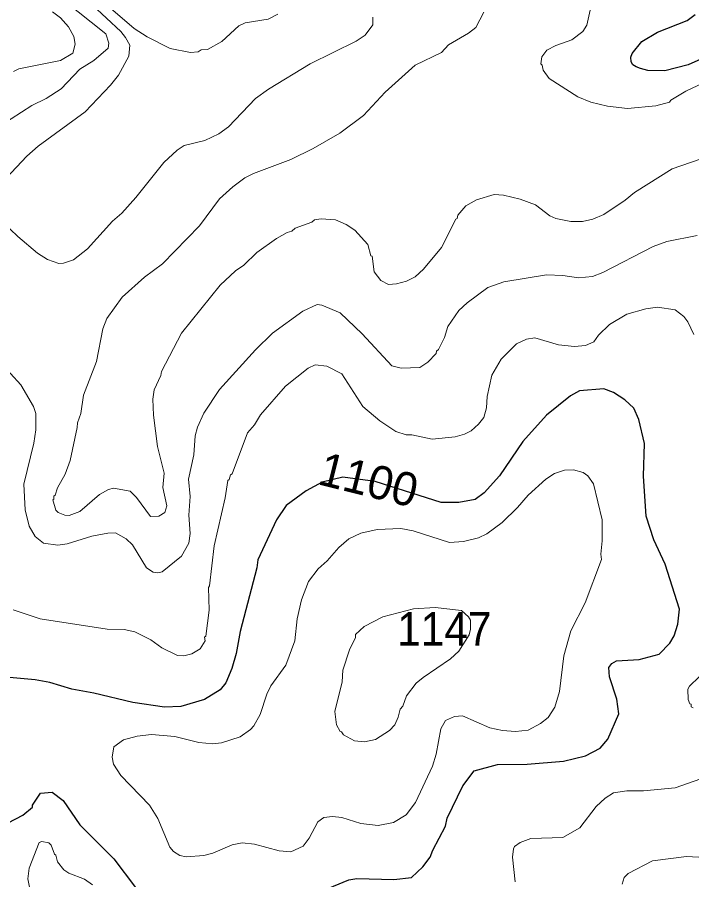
# Model space of a CAD drawing. Extents: x 447.8 to 473.9, y 7733.1 to 7760.8.
# Drawn here: x 470.955 to 472.572, y 7751.643 to 7753.711 of the extents above; entities that cross this region are included whole.
import ezdxf
from ezdxf.enums import TextEntityAlignment as Align

# ---------------------------------------------------------------- set-up
doc = ezdxf.new("R2010")
doc.units = 0
doc.header["$LTSCALE"] = 0.032
doc.layers.add('1', color=7, linetype='Continuous', lineweight=25)
doc.layers.add('2', color=7, linetype='Continuous', lineweight=13)
doc.layers.add('21', color=7, linetype='Continuous')
doc.layers.add('61', color=7, linetype='Continuous')

msp = doc.modelspace()

# ---------------------------------------------------------------- linework, layer by layer
at = {"layer": '1'}
for points in [[(472.9088, 7753.745), (472.8961, 7753.7065), (472.881, 7753.6353), (472.8769, 7753.6269), (472.852, 7753.6004), (472.8228, 7753.6073), (472.749, 7753.6401), (472.711, 7753.6473), (472.6487, 7753.6351), (472.5631, 7753.597), (472.5076, 7753.5821), (472.4669, 7753.5833), (472.4495, 7753.5877), (472.4391, 7753.5922), (472.4305, 7753.5972), (472.4266, 7753.604), (472.4257, 7753.6151), (472.4289, 7753.6242), (472.4527, 7753.6529), (472.4902, 7753.6754), (472.5608, 7753.7035), (472.5805, 7753.7173)], [(472.446, 7752.171), (472.4942, 7752.1843), (472.5192, 7752.2108), (472.5298, 7752.2278), (472.5387, 7752.2562), (472.5426, 7752.292), (472.5084, 7752.3995), (472.4809, 7752.4579), (472.4626, 7752.5153), (472.4561, 7752.611), (472.4585, 7752.6888), (472.4455, 7752.7469), (472.4329, 7752.7734), (472.412, 7752.7938), (472.3847, 7752.8114), (472.3611, 7752.8201), (472.3031, 7752.8154), (472.2815, 7752.8034), (472.224, 7752.757), (472.1673, 7752.6935), (472.1112, 7752.6117), (472.074, 7752.5712), (472.0526, 7752.5549), (472.0137, 7752.5478), (471.9712, 7752.548), (471.8134, 7752.5984), (471.7358, 7752.6081), (471.6858, 7752.5963), (471.6476, 7752.5759), (471.5998, 7752.5403), (471.5769, 7752.5063), (471.532, 7752.4102), (471.5295, 7752.391), (471.4894, 7752.2387), (471.4797, 7752.1854), (471.4691, 7752.1494), (471.4551, 7752.1152), (471.4417, 7752.0986), (471.4041, 7752.0754), (471.3472, 7752.0587), (471.3082, 7752.0572), (471.2317, 7752.0684), (471.1388, 7752.0909), (471.0859, 7752.1005), (471.033, 7752.1165), (470.9977, 7752.1229), (470.9278, 7752.1293)], [(471.6897, 7751.6186), (471.7496, 7751.6434), (471.7688, 7751.6467), (471.8581, 7751.6443), (471.8998, 7751.649), (471.9276, 7751.6746), (471.9449, 7751.6971), (471.9512, 7751.7143), (471.9815, 7751.7718), (471.9855, 7751.7907), (472.0229, 7751.8687), (472.0502, 7751.9041), (472.1066, 7751.9193), (472.1771, 7751.9201), (472.2645, 7751.9274), (472.3177, 7751.9403), (472.3525, 7751.9591), (472.3706, 7751.98), (472.3974, 7752.0408), (472.3928, 7752.0761), (472.3751, 7752.1297), (472.3736, 7752.1522), (472.3803, 7752.1615), (472.3916, 7752.1682), (472.446, 7752.171)], [(470.9332, 7751.7801), (470.968, 7751.7981), (470.9913, 7751.8174), (470.9919, 7751.8224), (471.0107, 7751.8508), (471.0384, 7751.8529), (471.0648, 7751.8333), (471.1052, 7751.7753), (471.1869, 7751.6935), (471.2387, 7751.6249), (471.26, 7751.6045), (471.2943, 7751.5812), (471.3126, 7751.573), (471.3483, 7751.5698), (471.3969, 7751.5746), (471.4292, 7751.5577), (471.4444, 7751.5285), (471.4469, 7751.5104), (471.4387, 7751.4728), (471.4326, 7751.4199), (471.4358, 7751.3819), (471.4446, 7751.3631), (471.4615, 7751.3423), (471.4764, 7751.3382)]]:
    msp.add_lwpolyline(points, dxfattribs=at)
at = {"layer": '2'}
for points in [[(471.0656, 7753.7523), (471.1675, 7753.6712), (471.1743, 7753.6491), (471.1728, 7753.637), (471.1385, 7753.6073), (471.1052, 7753.5862)], [(470.9281, 7753.325), (470.9776, 7753.3778), (471.005, 7753.4015), (471.118, 7753.4845), (471.1786, 7753.5484), (471.1978, 7753.5724), (471.2226, 7753.6177), (471.2248, 7753.644), (471.2148, 7753.6625), (471.2029, 7753.6767), (471.1349, 7753.7405)], [(471.5794, 7753.7182), (471.5569, 7753.7066), (471.5014, 7753.6972), (471.486, 7753.6905), (471.4454, 7753.6531), (471.4113, 7753.6333), (471.3955, 7753.6331), (471.3885, 7753.6283), (471.3703, 7753.6267), (471.3215, 7753.6356), (471.2664, 7753.6641), (471.235, 7753.6838), (471.1672, 7753.742)], [(471.8077, 7753.7111), (471.8076, 7753.6928), (471.7891, 7753.6676), (471.7673, 7753.6538), (471.657, 7753.5994), (471.5575, 7753.5384), (471.526, 7753.5158), (471.4611, 7753.4485), (471.4379, 7753.4314), (471.4049, 7753.4157), (471.3548, 7753.4034), (471.3387, 7753.3926), (471.3061, 7753.3628), (471.239, 7753.2785), (471.2054, 7753.2409), (471.1831, 7753.2218), (471.1233, 7753.1556), (471.0898, 7753.1291), (471.066, 7753.121), (471.0548, 7753.1209), (471.0273, 7753.1302), (471.0037, 7753.1453), (470.9561, 7753.1852), (470.9196, 7753.2202)], [(470.9462, 7753.5805), (470.9584, 7753.5874), (471.0583, 7753.6072), (471.0881, 7753.6248), (471.0942, 7753.646), (471.091, 7753.6648), (471.0779, 7753.6878), (471.0584, 7753.7098), (471.0397, 7753.7236)], [(471.2802, 7752.7951), (471.2819, 7752.7574), (471.2915, 7752.6821), (471.3074, 7752.6182), (471.3043, 7752.5839), (471.3139, 7752.5394), (471.3088, 7752.5234), (471.2946, 7752.5149), (471.2746, 7752.5141), (471.2409, 7752.5599), (471.2256, 7752.5749), (471.1859, 7752.5823), (471.1741, 7752.5788), (471.1525, 7752.5665), (471.1046, 7752.5262), (471.0798, 7752.5165), (471.0688, 7752.5172), (471.0527, 7752.5238), (471.0474, 7752.5292), (471.0399, 7752.554), (471.0429, 7752.556), (471.043, 7752.5626), (471.0462, 7752.5651), (471.0518, 7752.5832), (471.0695, 7752.6153), (471.0821, 7752.6487), (471.099, 7752.7273), (471.0991, 7752.7385), (471.107, 7752.7609), (471.1136, 7752.8048), (471.1447, 7752.886), (471.1602, 7752.9636), (471.1696, 7752.9886), (471.2065, 7753.0399), (471.2599, 7753.0878), (471.3035, 7753.1201), (471.3922, 7753.2112), (471.4399, 7753.2758), (471.4715, 7753.3045), (471.5007, 7753.326), (471.5217, 7753.3366), (471.6108, 7753.3699), (471.6643, 7753.3963), (471.7282, 7753.4332), (471.7854, 7753.4754), (471.8373, 7753.5313), (471.9086, 7753.5961), (471.9721, 7753.6263), (471.9885, 7753.6448), (472.0368, 7753.6724), (472.0545, 7753.6867), (472.0737, 7753.7229)], [(472.3285, 7753.7276), (472.3202, 7753.6918), (472.311, 7753.6771), (472.2849, 7753.6569), (472.2466, 7753.6433), (472.2247, 7753.6322), (472.213, 7753.6164), (472.2101, 7753.599), (472.2132, 7753.5963), (472.2161, 7753.5842)], [(471.1052, 7753.5862), (471.0599, 7753.5396), (471.0239, 7753.5162), (470.9903, 7753.4994), (470.9159, 7753.4518), (470.8829, 7753.4407)], [(472.2161, 7753.5842), (472.2305, 7753.5644), (472.2992, 7753.5199), (472.3302, 7753.5077), (472.37, 7753.4977), (472.4178, 7753.492)], [(472.4178, 7753.492), (472.486, 7753.4985), (472.5186, 7753.5077), (472.5217, 7753.5124), (472.5577, 7753.5335), (472.6277, 7753.5665)], [(472.5919, 7753.371), (472.5253, 7753.3474), (472.4346, 7753.2911), (472.4123, 7753.2725), (472.3614, 7753.2382), (472.3353, 7753.2268), (472.3101, 7753.2212), (472.2818, 7753.2212), (472.2464, 7753.2287), (472.2321, 7753.235), (472.1972, 7753.2611), (472.161, 7753.2745), (472.1209, 7753.2842), (472.0986, 7753.2859), (472.0558, 7753.273), (472.0305, 7753.2588), (472.0109, 7753.2367), (472.0095, 7753.2286), (472.0061, 7753.2266), (471.9721, 7753.1588), (471.9292, 7753.107), (471.9091, 7753.089), (471.8884, 7753.0786), (471.8642, 7753.0717), (471.8452, 7753.0705), (471.827, 7753.0799), (471.811, 7753.1004), (471.806, 7753.138), (471.8029, 7753.139), (471.7955, 7753.1665), (471.7646, 7753.2008), (471.7437, 7753.2137), (471.7178, 7753.225), (471.6834, 7753.2274), (471.6676, 7753.2251), (471.6612, 7753.22), (471.6216, 7753.2056), (471.6133, 7753.1978), (471.6024, 7753.1948), (471.5769, 7753.1805), (471.5292, 7753.147), (471.498, 7753.1165), (471.4779, 7753.103), (471.4414, 7753.0688)], [(470.9996, 7752.7217), (470.9949, 7752.6895), (470.9707, 7752.5913), (470.974, 7752.5298), (470.9837, 7752.4913), (470.998, 7752.466), (471.0181, 7752.45), (471.0521, 7752.4452), (471.0746, 7752.4483), (471.1339, 7752.4667), (471.1724, 7752.4739), (471.1906, 7752.4746), (471.2162, 7752.4609), (471.2312, 7752.4459), (471.265, 7752.3907), (471.2811, 7752.3806), (471.2918, 7752.3788), (471.3026, 7752.3816), (471.3489, 7752.4192), (471.3667, 7752.4503), (471.3692, 7752.473), (471.366, 7752.5176), (471.3692, 7752.562), (471.3652, 7752.6038), (471.378, 7752.6619), (471.3813, 7752.7071), (471.3873, 7752.7282), (471.4025, 7752.7619), (471.4402, 7752.8184), (471.5262, 7752.914), (471.5671, 7752.9533), (471.6398, 7753.0066), (471.6743, 7753.0223), (471.6848, 7753.0204), (471.729, 7753.0022), (471.7817, 7752.952), (471.8534, 7752.8756), (471.8751, 7752.8695), (471.9203, 7752.8713), (471.9396, 7752.8842), (471.9595, 7752.9048), (471.9601, 7752.9107), (471.9646, 7752.9141), (471.979, 7752.9434), (471.9875, 7752.9699), (472.0135, 7753.0076), (472.0334, 7753.0267), (472.0831, 7753.063), (472.1218, 7753.0767), (472.2241, 7753.0936), (472.2633, 7753.092), (472.3007, 7753.0864), (472.334, 7753.0898), (472.3588, 7753.0991), (472.4796, 7753.1611), (472.5127, 7753.1736), (472.5847, 7753.1881)], [(471.4414, 7753.0688), (471.3488, 7752.9539), (471.3004, 7752.8613), (471.2993, 7752.8521), (471.2831, 7752.818), (471.2802, 7752.7951)], [(470.9454, 7752.2903), (471.0096, 7752.2687), (471.1706, 7752.2444), (471.2116, 7752.2431), (471.2366, 7752.2376), (471.275, 7752.2184), (471.3013, 7752.1989), (471.3392, 7752.1808), (471.3541, 7752.1798), (471.3737, 7752.1845), (471.3938, 7752.1967), (471.4052, 7752.2161), (471.4038, 7752.2246), (471.4068, 7752.2275), (471.4148, 7752.2896), (471.4132, 7752.3436), (471.4158, 7752.3479), (471.4269, 7752.4439), (471.4533, 7752.5586), (471.4598, 7752.6004), (471.4629, 7752.6026), (471.4663, 7752.6141), (471.4699, 7752.6164), (471.5068, 7752.7147), (471.524, 7752.7339), (471.5383, 7752.7577), (471.5979, 7752.8268), (471.6527, 7752.87), (471.6696, 7752.8778), (471.697, 7752.8747), (471.7328, 7752.8562), (471.7838, 7752.7775), (471.8239, 7752.7431), (471.8624, 7752.7175), (471.8874, 7752.7097), (471.901, 7752.7096), (471.95, 7752.6994), (472.0052, 7752.7049), (472.0276, 7752.7117), (472.043, 7752.7197), (472.061, 7752.7353), (472.0736, 7752.7512), (472.08, 7752.7746), (472.0818, 7752.8014), (472.0931, 7752.8526), (472.1151, 7752.8914), (472.1518, 7752.9278), (472.176, 7752.9396), (472.1955, 7752.9422), (472.253, 7752.9253), (472.291, 7752.9213), (472.3171, 7752.9244), (472.3372, 7752.9325), (472.3489, 7752.9488), (472.3749, 7752.9747), (472.4165, 7752.9989), (472.4618, 7753.012)], [(472.4618, 7753.012), (472.4901, 7753.0158), (472.5326, 7753.0099), (472.5528, 7752.9936), (472.5623, 7752.9811), (472.577, 7752.95)], [(470.914, 7752.8767), (470.939, 7752.8569), (470.9633, 7752.8301), (470.994, 7752.7777), (470.9996, 7752.7609), (470.9996, 7752.7217)], [(472.5897, 7752.1299), (472.5663, 7752.1071), (472.5628, 7752.1001), (472.5636, 7752.0752), (472.5676, 7752.0654), (472.5706, 7752.0641), (472.5709, 7752.0575), (472.5754, 7752.0553)], [(473.0463, 7751.9922), (473.0328, 7751.9875), (472.9981, 7751.982), (472.9687, 7751.9842), (472.9003, 7752.0157), (472.8503, 7752.0337), (472.8244, 7752.0395), (472.7974, 7752.0368), (472.7777, 7752.0251), (472.7632, 7752.0047), (472.7648, 7751.9286), (472.7807, 7751.8267), (472.7768, 7751.8013), (472.7679, 7751.7755), (472.7265, 7751.7264), (472.6935, 7751.7098), (472.6369, 7751.6986), (472.6037, 7751.6965), (472.5595, 7751.6988), (472.4777, 7751.6883), (472.4194, 7751.6587), (472.4102, 7751.6484), (472.4054, 7751.6324)], [(472.594, 7751.8851), (472.5326, 7751.864), (472.456, 7751.8568), (472.4161, 7751.8567), (472.3842, 7751.852), (472.3641, 7751.8392), (472.3433, 7751.8193), (472.304, 7751.7681), (472.2626, 7751.7445), (472.1859, 7751.7421), (472.161, 7751.7328), (472.1474, 7751.7234), (472.1444, 7751.7176), (472.1427, 7751.6973), (472.149, 7751.6383)], [(471.135, 7751.6315), (471.1163, 7751.6445), (471.0785, 7751.6594), (471.0667, 7751.667), (471.0512, 7751.686), (471.0477, 7751.7025), (471.0446, 7751.7048), (471.0366, 7751.7265), (471.0303, 7751.7322), (471.0141, 7751.7348), (471.0077, 7751.7324), (470.9836, 7751.6712), (470.9804, 7751.6455), (470.9956, 7751.5686)]]:
    msp.add_lwpolyline(points, dxfattribs=at)
for points in [[(472.2549, 7752.0943), (472.265, 7752.1801), (472.2823, 7752.2402), (472.3168, 7752.3075), (472.3558, 7752.4107), (472.3543, 7752.424), (472.3576, 7752.4557), (472.3575, 7752.5063), (472.3366, 7752.5926), (472.3227, 7752.6113), (472.3118, 7752.6198), (472.2885, 7752.6262), (472.2668, 7752.6255), (472.2434, 7752.6173), (472.222, 7752.6038), (472.18, 7752.565), (472.1545, 7752.5355), (472.1176, 7752.4994), (472.0804, 7752.4725), (472.0606, 7752.4631), (472.0245, 7752.4545), (471.9916, 7752.4516), (471.9038, 7752.4796), (471.8749, 7752.4852), (471.8179, 7752.4829), (471.779, 7752.474), (471.75, 7752.4603), (471.7256, 7752.4401), (471.6983, 7752.408), (471.6767, 7752.3888), (471.6534, 7752.3579), (471.6361, 7752.314), (471.6257, 7752.2691), (471.6201, 7752.2162), (471.5989, 7752.1575), (471.5632, 7752.1084), (471.5533, 7752.0886), (471.5375, 7752.0396), (471.5222, 7752.0123), (471.514, 7752.0032), (471.4895, 7751.9856), (471.445, 7751.9714), (471.424, 7751.969), (471.3904, 7751.972), (471.3327, 7751.9867), (471.2766, 7751.9914), (471.2426, 7751.9873), (471.2094, 7751.9785), (471.1862, 7751.9622), (471.1824, 7751.9374), (471.1858, 7751.9203), (471.203, 7751.8931), (471.2719, 7751.8218), (471.2924, 7751.7904), (471.3211, 7751.7211), (471.3296, 7751.7111), (471.3449, 7751.7018), (471.3598, 7751.698), (471.4023, 7751.7013), (471.4238, 7751.7074), (471.4704, 7751.7273), (471.4944, 7751.7318), (471.5235, 7751.7286), (471.5826, 7751.713), (471.6107, 7751.7101), (471.6403, 7751.724), (471.6552, 7751.7427), (471.6757, 7751.7825), (471.6898, 7751.7926), (471.7107, 7751.795), (471.7335, 7751.7927), (471.7784, 7751.7783), (471.8204, 7751.7735), (471.857, 7751.7805), (471.8875, 7751.7988), (471.9096, 7751.8283), (471.9502, 7751.9157), (471.9591, 7751.9446), (471.9703, 7752.0048), (471.9818, 7752.0249), (472.0029, 7752.0346), (472.0227, 7752.0362), (472.0881, 7752.0075), (472.1181, 7752.0015), (472.1492, 7751.999), (472.18, 7752.0019), (472.2095, 7752.0175), (472.2279, 7752.0324), (472.2438, 7752.0574)], [(471.8475, 7752.0008), (471.8603, 7752.0144), (471.8685, 7752.0331), (471.873, 7752.0524), (471.879, 7752.0598), (471.8885, 7752.0841), (471.9116, 7752.1146), (471.9278, 7752.1285), (471.9936, 7752.1731), (472.0133, 7752.1916), (472.0384, 7752.2305), (472.0415, 7752.2442), (472.0416, 7752.2652), (472.0367, 7752.2737), (472.0204, 7752.2885), (471.957, 7752.296), (471.9046, 7752.2928), (471.8315, 7752.2738), (471.7863, 7752.2508), (471.7663, 7752.2315), (471.7658, 7752.224), (471.7513, 7752.1944), (471.7352, 7752.1459), (471.7338, 7752.1181), (471.7164, 7752.0469), (471.7207, 7752.0149), (471.729, 7751.999), (471.7323, 7751.9983), (471.7374, 7751.9906), (471.7633, 7751.9767), (471.7872, 7751.9739), (471.814, 7751.9795)]]:
    msp.add_lwpolyline(points, close=True, dxfattribs=at)

# ---------------------------------------------------------------- texts
at = {"layer": '21', "width": 0.95}
msp.add_text('1147', height=0.08, dxfattribs=at).set_placement((471.8658, 7752.2048))
at = {"layer": '61'}
msp.add_text('1100', height=0.08, rotation=346.107, dxfattribs=at).set_placement((471.7879, 7752.5635), align=Align.CENTER)

doc.saveas('drawing.dxf')
